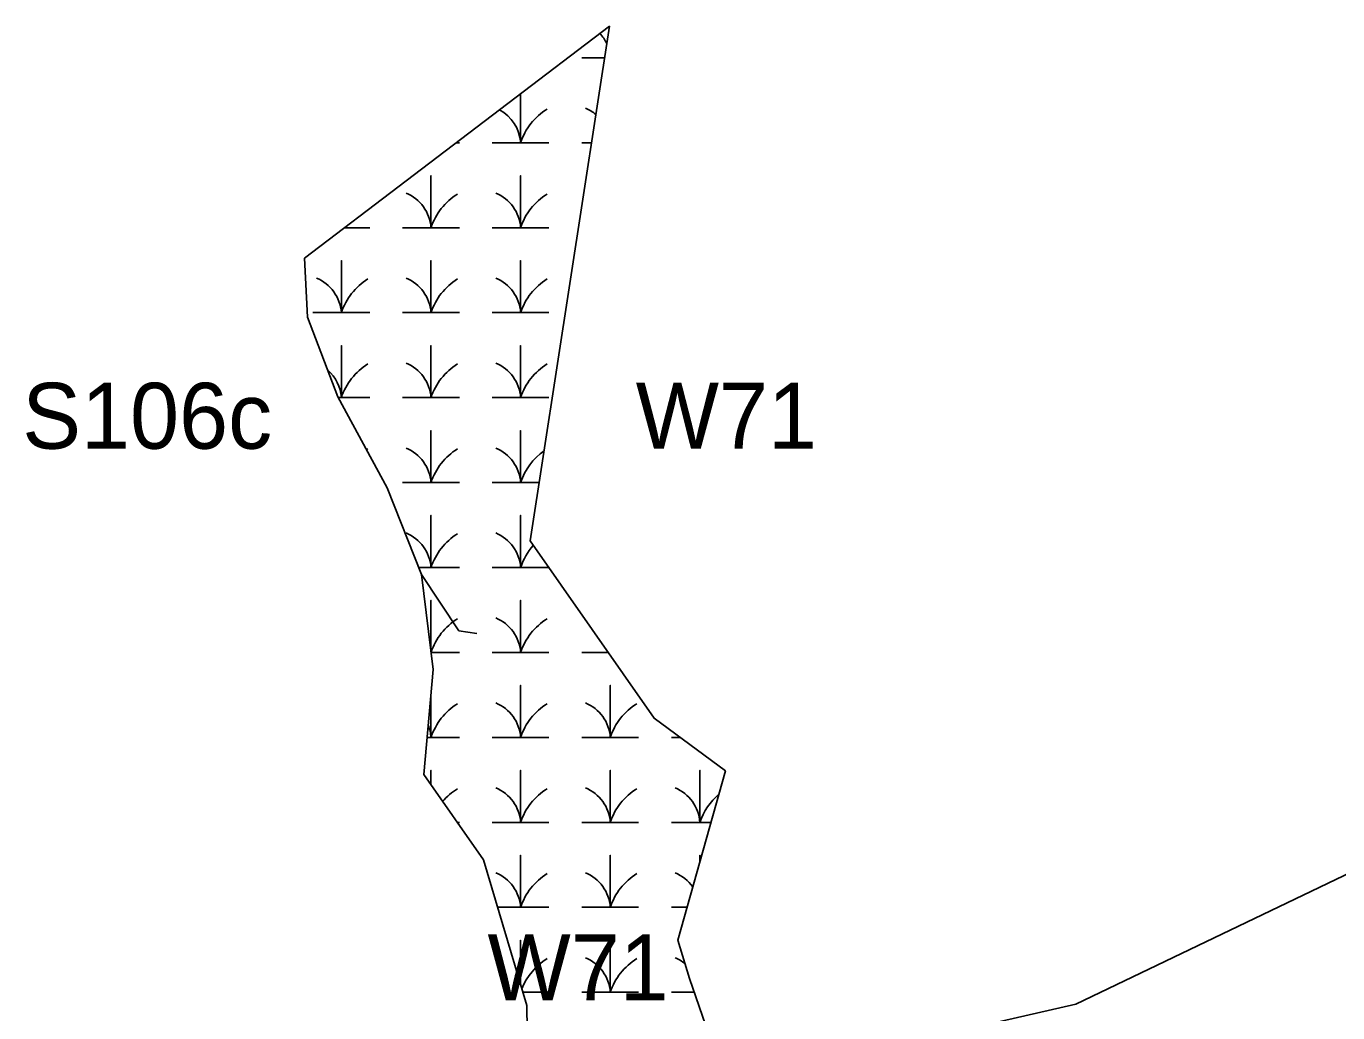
# Model space of a CAD drawing. Extents: x 1253697 to 1278588, y 912189 to 981699.
# Drawn here: x 1259946.9 to 1260344.8, y 961232.3 to 961531.7 of the extents above; entities that cross this region are included whole.
import ezdxf

# ---------------------------------------------------------------- set-up
doc = ezdxf.new("R2010")
doc.units = 0
for name, color, linetype in [('Default', 7, 'Continuous'), ('Exist Environmental Wetland Boundary', 7, 'Continuous'), ('Exist Environmental Wetland Boundary Cogo Number', 7, 'Continuous'), ('Exist Hydro Jurisdictional Stream or Body of Water Mitigable', 7, 'Continuous')]:
    doc.layers.add(name, color=color, linetype=linetype)

msp = doc.modelspace()

# ---------------------------------------------------------------- linework, layer by layer
at = {"layer": 'Default'}
msp.add_lwpolyline([(1260687.35, 961439.76), (1260607.93, 961399.12), (1260265.41, 961234.93), (1260161.34, 961211.11)], dxfattribs=at)
msp.add_lwpolyline([(1260687.35, 961439.76), (1260607.93, 961399.12), (1260265.41, 961234.93), (1260161.34, 961211.11)], dxfattribs=at)
at = {"layer": 'Exist Environmental Wetland Boundary'}
for p, q in [((1260115.5, 961522.09), (1260122.35, 961522.09)), ((1260077.41, 961496.31), (1260078.3, 961496.31)), ((1260115.5, 961496.31), (1260118.38, 961496.31)), ((1260043.55, 961470.53), (1260051.1, 961470.53)), ((1260069.72, 961341.63), (1260078.3, 961341.63)), ((1260115.5, 961341.63), (1260123.45, 961341.63)), ((1260142.71, 961315.85), (1260145.29, 961315.85)), ((1260077.63, 961290.07), (1260078.3, 961290.07)), ((1260142.71, 961264.29), (1260147.37, 961264.29)), ((1260097.59, 961238.51), (1260105.5, 961238.51)), ((1260142.71, 961238.51), (1260149.57, 961238.51))]:
    msp.add_line(p, q, dxfattribs=at)
for points in [[(1260159.75, 961209.02), (1260148.13, 961242.68), (1260144.56, 961254.32), (1260159.05, 961305.68), (1260137.41, 961321.68), (1260099.79, 961375.45), (1260123.82, 961531.66), (1260031.35, 961461.24), (1260032.22, 961443.35), (1260041.46, 961419.21), (1260056.38, 961391.6), (1260066.77, 961365.28), (1260070.37, 961336.43), (1260067.49, 961304.57), (1260085.61, 961278.65), (1260098.78, 961234.53), (1260099.43, 961189.63)], [(1260088.3, 961496.31), (1260096.9, 961496.31), (1260096.9, 961511.16)], [(1260096.9, 961511.16), (1260096.9, 961496.31), (1260105.5, 961496.31)], [(1260061.1, 961470.53), (1260069.7, 961470.53), (1260069.7, 961486.31), (1260069.7, 961470.53), (1260078.3, 961470.53)], [(1260088.3, 961470.53), (1260096.9, 961470.53), (1260096.9, 961486.31), (1260096.9, 961470.53), (1260105.5, 961470.53)], [(1260033.89, 961444.75), (1260042.5, 961444.75), (1260042.5, 961460.53), (1260042.5, 961444.75), (1260051.1, 961444.75)], [(1260061.1, 961444.75), (1260069.7, 961444.75), (1260069.7, 961460.53), (1260069.7, 961444.75), (1260078.3, 961444.75)], [(1260088.3, 961444.75), (1260096.9, 961444.75), (1260096.9, 961460.53), (1260096.9, 961444.75), (1260105.5, 961444.75)], [(1260041.59, 961418.97), (1260042.5, 961418.97), (1260042.5, 961434.75), (1260042.5, 961418.97), (1260051.1, 961418.97)], [(1260061.1, 961418.97), (1260069.7, 961418.97), (1260069.7, 961434.75), (1260069.7, 961418.97), (1260078.3, 961418.97)], [(1260088.3, 961418.97), (1260096.9, 961418.97), (1260096.9, 961434.75), (1260096.9, 961418.97), (1260105.5, 961418.97)], [(1260061.1, 961393.19), (1260069.7, 961393.19), (1260069.7, 961408.97), (1260069.7, 961393.19), (1260078.3, 961393.19)], [(1260088.3, 961393.19), (1260096.9, 961393.19), (1260096.9, 961408.97), (1260096.9, 961393.19), (1260102.52, 961393.19)], [(1260065.93, 961367.41), (1260069.7, 961367.41), (1260069.7, 961383.19), (1260069.7, 961367.41), (1260078.3, 961367.41)], [(1260088.3, 961367.41), (1260096.9, 961367.41), (1260096.9, 961383.19), (1260096.9, 961367.41), (1260105.42, 961367.41)], [(1260069.7, 961341.8), (1260069.7, 961357.41), (1260069.7, 961341.8)], [(1260088.3, 961341.63), (1260096.9, 961341.63), (1260096.9, 961357.41), (1260096.9, 961341.63), (1260105.5, 961341.63)], [(1260068.51, 961315.85), (1260069.7, 961315.85), (1260069.7, 961329.01)], [(1260069.7, 961329.01), (1260069.7, 961315.85), (1260078.3, 961315.85)], [(1260088.3, 961315.85), (1260096.9, 961315.85), (1260096.9, 961331.63), (1260096.9, 961315.85), (1260105.5, 961315.85)], [(1260115.5, 961315.85), (1260124.11, 961315.85), (1260124.11, 961331.63), (1260124.11, 961315.85), (1260132.71, 961315.85)], [(1260069.7, 961301.41), (1260069.7, 961305.85), (1260069.7, 961301.41)], [(1260088.3, 961290.07), (1260096.9, 961290.07), (1260096.9, 961305.85), (1260096.9, 961290.07), (1260105.5, 961290.07)], [(1260115.5, 961290.07), (1260124.11, 961290.07), (1260124.11, 961305.85), (1260124.11, 961290.07), (1260132.71, 961290.07)], [(1260142.71, 961290.07), (1260151.31, 961290.07), (1260151.31, 961305.85), (1260151.31, 961290.07), (1260154.65, 961290.07)], [(1260089.9, 961264.29), (1260096.9, 961264.29), (1260096.9, 961280.07), (1260096.9, 961264.29), (1260105.5, 961264.29)], [(1260115.5, 961264.29), (1260124.11, 961264.29), (1260124.11, 961280.07), (1260124.11, 961264.29), (1260132.71, 961264.29)], [(1260151.31, 961278.24), (1260151.31, 961280.07), (1260151.31, 961278.24)], [(1260096.9, 961240.81), (1260096.9, 961254.29), (1260096.9, 961240.81)], [(1260115.5, 961238.51), (1260124.11, 961238.51), (1260124.11, 961254.29), (1260124.11, 961238.51), (1260132.71, 961238.51)]]:
    msp.add_lwpolyline(points, dxfattribs=at)
for centre, radius, start, end in [((1260111.84, 961521.21), 12.3, 24.7819, 42.2253), ((1260084.64, 961495.43), 12.3, 4.1403, 61.7198), ((1260115.14, 961490.25), 19.22, 122.1274, 161.6222), ((1260111.84, 961495.43), 12.3, 50.2611, 67.535), ((1260057.43, 961469.65), 12.3, 4.1403, 67.535), ((1260087.94, 961464.47), 19.22, 122.1274, 161.6222), ((1260084.64, 961469.65), 12.3, 4.1403, 67.535), ((1260115.14, 961464.47), 19.22, 122.1274, 161.6222), ((1260030.23, 961443.87), 12.3, 4.1403, 67.535), ((1260060.74, 961438.69), 19.22, 122.1274, 161.6222), ((1260057.43, 961443.87), 12.3, 4.1403, 67.535), ((1260087.94, 961438.69), 19.22, 122.1274, 161.6222), ((1260084.64, 961443.87), 12.3, 4.1403, 67.535), ((1260115.14, 961438.69), 19.22, 122.1274, 161.6222), ((1260060.74, 961412.91), 19.22, 122.1274, 161.6222), ((1260057.43, 961418.08), 12.3, 4.1403, 67.535), ((1260087.94, 961412.91), 19.22, 122.1274, 161.6222), ((1260084.64, 961418.08), 12.3, 4.1403, 67.535), ((1260115.14, 961412.91), 19.22, 122.1274, 161.6222), ((1260030.23, 961418.08), 12.3, 4.1403, 48.5981), ((1260060.74, 961387.13), 19.22, 122.1274, 123.4766), ((1260057.43, 961392.3), 12.3, 4.1403, 67.535), ((1260087.94, 961387.13), 19.22, 122.1274, 161.6222), ((1260084.64, 961392.3), 12.3, 4.1403, 67.535), ((1260115.14, 961387.13), 19.22, 125.4371, 161.6222), ((1260057.43, 961366.52), 12.3, 4.1403, 67.535), ((1260087.94, 961361.35), 19.22, 122.1274, 161.6222), ((1260084.64, 961366.52), 12.3, 4.1403, 67.535), ((1260115.14, 961361.35), 19.22, 138.5034, 161.6222), ((1260087.94, 961335.57), 19.22, 122.1274, 161.4793), ((1260084.64, 961340.74), 12.3, 4.1403, 67.535), ((1260115.14, 961335.57), 19.22, 122.1274, 161.6222), ((1260087.94, 961309.79), 19.22, 122.1274, 161.6222), ((1260084.64, 961314.96), 12.3, 4.1403, 67.535), ((1260115.14, 961309.79), 19.22, 122.1274, 161.6222), ((1260111.84, 961314.96), 12.3, 4.1403, 67.535), ((1260142.35, 961309.79), 19.22, 122.1274, 161.6222), ((1260057.43, 961314.96), 12.3, 4.1403, 21.8906), ((1260087.94, 961284.01), 19.22, 122.1274, 139.9699), ((1260084.64, 961289.18), 12.3, 4.1403, 67.535), ((1260115.14, 961284.01), 19.22, 122.1274, 161.6222), ((1260111.84, 961289.18), 12.3, 4.1403, 67.535), ((1260142.35, 961284.01), 19.22, 122.1274, 161.6222), ((1260139.04, 961289.18), 12.3, 4.1403, 67.535), ((1260169.55, 961284.01), 19.22, 130.5393, 161.6222), ((1260084.64, 961263.4), 12.3, 4.1403, 67.535), ((1260115.14, 961258.23), 19.22, 122.1274, 161.6222), ((1260111.84, 961263.4), 12.3, 4.1403, 67.535), ((1260142.35, 961258.23), 19.22, 122.1274, 161.6222), ((1260139.04, 961263.4), 12.3, 35.0249, 67.535), ((1260115.14, 961232.45), 19.22, 122.1274, 158.3358), ((1260111.84, 961237.62), 12.3, 4.1403, 67.535), ((1260142.35, 961232.45), 19.22, 122.1274, 161.6222), ((1260139.04, 961237.62), 12.3, 51.2435, 67.535)]:
    msp.add_arc(centre, radius, start, end, dxfattribs=at)
at = {"layer": 'Exist Hydro Jurisdictional Stream or Body of Water Mitigable'}
msp.add_lwpolyline([(1260083.61, 961347.37), (1260078.19, 961348.18), (1260066.77, 961365.28), (1260056.38, 961391.6), (1260041.46, 961419.21), (1260032.22, 961443.35)], dxfattribs=at)

# ---------------------------------------------------------------- texts
at = {"layer": 'Exist Environmental Wetland Boundary'}
for s, p in [('S106c', (1259945.67, 961403.45)), ('W71', (1260131.83, 961403.45))]:
    msp.add_text(s, height=20, dxfattribs=at).set_placement(p)
at = {"layer": 'Exist Environmental Wetland Boundary Cogo Number'}
msp.add_text('W71', height=20, dxfattribs=at).set_placement((1260086.86, 961236.05))

doc.saveas('drawing.dxf')
